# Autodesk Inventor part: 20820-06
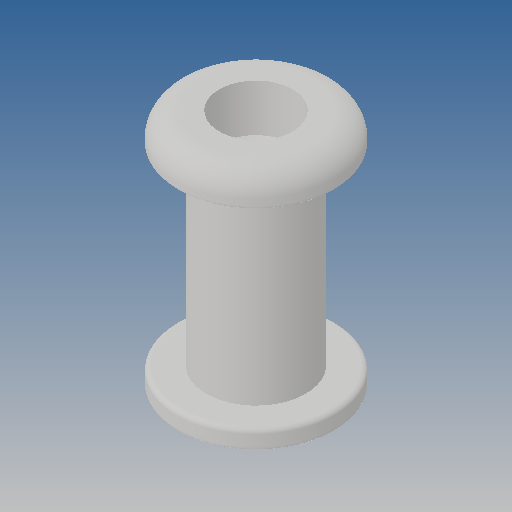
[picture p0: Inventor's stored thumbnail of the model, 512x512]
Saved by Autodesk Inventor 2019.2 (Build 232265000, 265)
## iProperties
Created: 2011-12
Part Number: 20820-06
Material: Ogólny
Document SubType Name: Modeling
Designer: CADENGINEERING4
Density: 1 g/cm^3
Appearance: Domyślna
Author: CADENGINEERING4
Revision Number: ÈÎºÎ
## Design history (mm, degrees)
feature "Ðý×ª1"
node "Bryła1"
